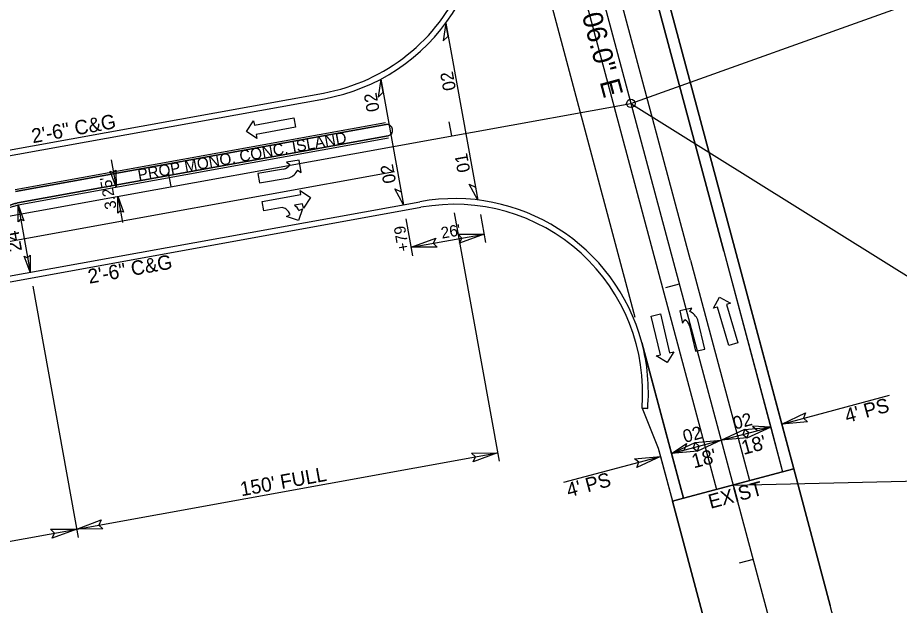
# Model space of a CAD drawing. Extents: x 1616561 to 1622460, y 896726 to 899651.
# Drawn here: x 1621262.4 to 1621571.6, y 898035.6 to 898241.6 of the extents above; entities that cross this region are included whole.
import ezdxf

# ---------------------------------------------------------------- set-up
doc = ezdxf.new("R2010")
doc.units = 0
for name, color, linetype in [('Exist Boundary Study Area', 7, 'Continuous'), ('Old_Level_3', 7, 'Continuous'), ('Old_Level_40', 7, 'Continuous'), ('Prop Dimension', 7, 'Continuous'), ('Prop Horizontal Alignment', 7, 'Continuous'), ('Prop Horizontal Alignment Tick Small', 7, 'Continuous'), ('Prop Lane Arrow CELL', 7, 'Continuous'), ('Prop North Arrow NAD83 for Plan Sheets CELL', 7, 'Continuous'), ('Prop Shade Light', 7, 'Continuous'), ('Prop Shade Medium', 7, 'Continuous'), ('Prop Superelevation  Arrow CELL', 7, 'Continuous'), ('Prop Terminator CELL', 7, 'Continuous'), ('Scratch_Level_1', 7, 'Continuous'), ('Sheet Cutting Line CELL', 7, 'Continuous'), ('Sheet North Arrow CELL', 7, 'Continuous'), ('Sheet Sticker Preliminary CELL', 7, 'Continuous')]:
    doc.layers.add(name, color=color, linetype=linetype)

msp = doc.modelspace()

# ---------------------------------------------------------------- linework, layer by layer
at = {"layer": 'Exist Boundary Study Area'}
for p, q in [((1621261.67, 898180.63), (1621391.56, 898204.14)), ((1621392.28, 898200.21), (1621262.39, 898176.7))]:
    msp.add_line(p, q, dxfattribs=at)
msp.add_arc((1621391.92, 898202.18), 2, 280.2599, 100.2599, dxfattribs=at)
msp.add_spline([(1621262.39, 898176.7), (1621261.08, 898176.3), (1621260.43, 898176.1), (1621259.78, 898175.9), (1621259.13, 898175.7), (1621258.48, 898175.5), (1621257.83, 898175.3), (1621257.18, 898175.1), (1621256.53, 898174.9), (1621255.88, 898174.7), (1621255.23, 898174.5), (1621254.58, 898174.3), (1621253.93, 898174.1), (1621253.28, 898173.9), (1621252.63, 898173.7), (1621251.98, 898173.5), (1621251.33, 898173.29), (1621250.68, 898173.09), (1621250.03, 898172.89), (1621249.38, 898172.69), (1621248.73, 898172.49), (1621248.08, 898172.29), (1621247.43, 898172.09), (1621246.78, 898171.89), (1621246.13, 898171.69), (1621245.47, 898171.49), (1621244.82, 898171.29), (1621244.17, 898171.09), (1621243.52, 898170.89), (1621242.87, 898170.69), (1621242.22, 898170.49), (1621241.57, 898170.29), (1621240.92, 898170.09), (1621240.27, 898169.89), (1621239.62, 898169.69), (1621238.97, 898169.49), (1621238.32, 898169.29), (1621237.67, 898169.09), (1621237.02, 898168.89), (1621236.37, 898168.69), (1621235.72, 898168.49), (1621235.07, 898168.29), (1621234.42, 898168.09), (1621233.77, 898167.89), (1621233.12, 898167.69), (1621232.47, 898167.49), (1621231.82, 898167.29), (1621231.17, 898167.09), (1621230.51, 898166.89), (1621229.86, 898166.69), (1621229.21, 898166.49), (1621228.56, 898166.29), (1621227.91, 898166.09), (1621227.26, 898165.89), (1621226.61, 898165.69), (1621225.96, 898165.49), (1621225.31, 898165.29), (1621224.66, 898165.09), (1621224.01, 898164.89), (1621223.36, 898164.69), (1621222.71, 898164.49), (1621222.06, 898164.29), (1621221.41, 898164.09), (1621220.76, 898163.89), (1621220.11, 898163.69), (1621219.46, 898163.49), (1621218.81, 898163.29), (1621218.16, 898163.09), (1621217.51, 898162.89), (1621216.86, 898162.69), (1621216.21, 898162.49), (1621215.55, 898162.29), (1621214.9, 898162.09), (1621214.25, 898161.89)], degree=3, dxfattribs=at)
at = {"layer": 'Old_Level_3'}
for p, q in [((1621498.38, 898156.58), (1621460.96, 898296.37)), ((1621449.37, 898293.27), (1621486.78, 898153.48)), ((1621437.78, 898290.17), (1621478.87, 898136.64)), ((1621261.54, 898181.37), (1621391.43, 898204.88)), ((1621262.52, 898175.96), (1621392.41, 898199.47)), ((1621166.26, 898146.34), (1621394.55, 898187.66)), ((1621498.38, 898156.58), (1621519.06, 898079.31)), ((1621486.78, 898153.48), (1621507.47, 898076.2))]:
    msp.add_line(p, q, dxfattribs=at)
msp.add_spline([(1621214.39, 898161.15), (1621215.04, 898161.35), (1621215.69, 898161.55), (1621216.34, 898161.75), (1621216.99, 898161.95), (1621217.64, 898162.15), (1621218.29, 898162.35), (1621218.94, 898162.55), (1621219.59, 898162.75), (1621220.24, 898162.95), (1621220.89, 898163.15), (1621221.54, 898163.35), (1621222.19, 898163.55), (1621222.84, 898163.75), (1621223.49, 898163.95), (1621224.14, 898164.15), (1621224.79, 898164.35), (1621225.44, 898164.55), (1621226.1, 898164.75), (1621226.75, 898164.95), (1621227.4, 898165.15), (1621228.05, 898165.35), (1621228.7, 898165.55), (1621229.35, 898165.75), (1621230, 898165.95), (1621230.65, 898166.15), (1621231.3, 898166.35), (1621231.95, 898166.55), (1621232.6, 898166.75), (1621233.25, 898166.95), (1621233.9, 898167.15), (1621234.55, 898167.35), (1621235.2, 898167.55), (1621235.85, 898167.75), (1621236.5, 898167.95), (1621237.15, 898168.15), (1621237.8, 898168.35), (1621238.45, 898168.55), (1621239.1, 898168.75), (1621239.75, 898168.95), (1621240.4, 898169.15), (1621241.06, 898169.35), (1621241.71, 898169.55), (1621242.36, 898169.76), (1621243.01, 898169.96), (1621243.66, 898170.16), (1621244.31, 898170.36), (1621244.96, 898170.56), (1621245.61, 898170.76), (1621246.26, 898170.96), (1621246.91, 898171.16), (1621247.56, 898171.36), (1621248.21, 898171.56), (1621248.86, 898171.76), (1621249.51, 898171.96), (1621250.16, 898172.16), (1621250.81, 898172.36), (1621251.46, 898172.56), (1621252.11, 898172.76), (1621252.76, 898172.96), (1621253.41, 898173.16), (1621254.06, 898173.36), (1621254.71, 898173.56), (1621255.36, 898173.76), (1621256.02, 898173.96), (1621256.67, 898174.16), (1621257.32, 898174.36), (1621257.97, 898174.56), (1621258.62, 898174.76), (1621259.27, 898174.96), (1621259.92, 898175.16), (1621260.57, 898175.36), (1621261.22, 898175.56), (1621262.52, 898175.96)], degree=3, dxfattribs=at)
at = {"layer": 'Old_Level_40'}
for p, q in [((1621530.65, 898082.41), (1621534.52, 898083.44)), ((1621534.52, 898083.44), (1621547.33, 898035.56)), ((1621495.88, 898073.1), (1621530.65, 898082.41)), ((1621492.01, 898072.07), (1621495.88, 898073.1)), ((1621502.92, 898031.33), (1621492.01, 898072.07))]:
    msp.add_line(p, q, dxfattribs=at)
at = {"layer": 'Prop Dimension'}
for p, q in [((1621295.18, 898191.72), (1621296.91, 898182.18)), ((1621297.49, 898178.99), (1621299.14, 898169.83)), ((1621262.52, 898175.96), (1621266.79, 898152.34)), ((1621415.45, 898173.21), (1621431.23, 898086.08)), ((1621267.68, 898147.42), (1621283.62, 898059.37)), ((1621530.32, 898099.12), (1621568.12, 898109.21)), ((1621509.07, 898093.44), (1621526.46, 898098.08)), ((1621491.68, 898088.79), (1621509.07, 898093.44)), ((1621283.09, 898062.32), (1621430.69, 898089.04)), ((1621453.92, 898078.71), (1621487.81, 898087.76)), ((1621184.69, 898044.51), (1621283.09, 898062.32))]:
    msp.add_line(p, q, dxfattribs=at)
at = {"layer": 'Prop Horizontal Alignment'}
for p, q in [((1621476.41, 898300.51), (1621513.83, 898160.72)), ((1621513.83, 898160.72), (1621534.52, 898083.44)), ((1621481.33, 898104.68), (1621487.05, 898090.62)), ((1621481.33, 898104.68), (1621483.33, 898104.52)), ((1621487.05, 898090.62), (1621492.01, 898072.07)), ((1621530.65, 898082.41), (1621534.52, 898083.44)), ((1621534.52, 898083.44), (1621547.33, 898035.56)), ((1621492.01, 898072.07), (1621495.88, 898073.1)), ((1621492.01, 898072.07), (1621502.92, 898031.33))]:
    msp.add_line(p, q, dxfattribs=at)
msp.add_arc((1621415.56, 898110.17), 68, 355.2351, 14.985, dxfattribs=at)
at = {"layer": 'Prop Horizontal Alignment Tick Small'}
for p, q in [((1621019.59, 898151.82), (1621369.62, 898215.16)), ((1621042.54, 898109.72), (1621403.81, 898175.11)), ((1621483.33, 898104.52), (1621481.33, 898104.68))]:
    msp.add_line(p, q, dxfattribs=at)
for centre, radius, start, end in [((1621357.86, 898280.11), 66, 280.2581, 33.5864), ((1621415.56, 898110.17), 66, 355.2351, 100.2599), ((1621415.56, 898110.17), 68, 355.2351, 14.985)]:
    msp.add_arc(centre, radius, start, end, dxfattribs=at)
at = {"layer": 'Prop Lane Arrow CELL'}
for p, q in [((1621345.42, 898203.95), (1621359.2, 898206.44)), ((1621359.2, 898206.44), (1621359.79, 898203.19)), ((1621342.62, 898201.71), (1621345.15, 898205.42)), ((1621345.15, 898205.42), (1621345.42, 898203.95)), ((1621346.28, 898199.22), (1621342.62, 898201.71)), ((1621359.79, 898203.19), (1621346.01, 898200.7)), ((1621346.01, 898200.7), (1621346.28, 898199.22)), ((1621361.08, 898191.67), (1621356.64, 898190.94)), ((1621356.64, 898190.94), (1621357.86, 898190.09)), ((1621361.8, 898187.33), (1621361.08, 898191.67)), ((1621355.6, 898188.52), (1621346.58, 898186.94)), ((1621360.58, 898188.18), (1621361.8, 898187.33)), ((1621346.58, 898186.94), (1621347.16, 898183.69)), ((1621347.16, 898183.69), (1621357.55, 898185.51)), ((1621348.16, 898177.13), (1621361.73, 898179.59)), ((1621361.73, 898179.59), (1621361.47, 898181.06)), ((1621361.47, 898181.06), (1621365.08, 898178.52)), ((1621365.08, 898178.52), (1621362.59, 898174.87)), ((1621348.74, 898173.88), (1621348.16, 898177.13)), ((1621362.32, 898176.34), (1621359.52, 898175.83)), ((1621362.59, 898174.87), (1621362.32, 898176.34)), ((1621355.09, 898175.03), (1621348.74, 898173.88)), ((1621356.67, 898171.91), (1621357.98, 898172.56)), ((1621362.33, 898174.62), (1621360.85, 898170.44)), ((1621360.97, 898173.96), (1621362.33, 898174.62)), ((1621360.85, 898170.44), (1621356.67, 898171.91)), ((1621506.37, 898139.71), (1621508.45, 898143.61)), ((1621508.45, 898143.61), (1621512.41, 898141.5)), ((1621512.41, 898141.5), (1621510.97, 898141.07)), ((1621498.84, 898139.79), (1621494.55, 898138.83)), ((1621494.55, 898138.83), (1621495.53, 898134.44)), ((1621498.06, 898138.53), (1621498.84, 898139.79)), ((1621507.8, 898140.13), (1621506.37, 898139.71)), ((1621511.77, 898126.71), (1621507.8, 898140.13)), ((1621510.97, 898141.07), (1621514.94, 898127.64)), ((1621484.57, 898136.97), (1621487.78, 898137.73)), ((1621487.79, 898123.35), (1621484.57, 898136.97)), ((1621487.78, 898137.73), (1621491, 898124.11)), ((1621495.53, 898134.44), (1621496.32, 898135.7)), ((1621503.33, 898125.39), (1621500.9, 898135.65)), ((1621498.01, 898133.53), (1621500.12, 898124.63)), ((1621514.94, 898127.64), (1621511.77, 898126.71)), ((1621486.33, 898123), (1621487.79, 898123.35)), ((1621490.17, 898120.68), (1621486.33, 898123)), ((1621492.46, 898124.45), (1621490.17, 898120.68)), ((1621491, 898124.11), (1621492.46, 898124.45)), ((1621500.12, 898124.63), (1621503.33, 898125.39))]:
    msp.add_line(p, q, dxfattribs=at)
for centre, radius, start, end in [((1621355.04, 898191.73), 3.28, 279.9792, 329.6374), ((1621355.87, 898190.47), 5.25, 288.6553, 333.967), ((1621356.85, 898172.31), 4.43, 21.8508, 52.7294), ((1621354.9, 898172.51), 2.52, 49.3331, 85.6451), ((1621353.86, 898170.9), 4.43, 21.9696, 52.8232), ((1621496.04, 898133.69), 5.25, 21.9812, 67.2929), ((1621494.84, 898132.79), 3.28, 13.3051, 62.9633)]:
    msp.add_arc(centre, radius, start, end, dxfattribs=at)
at = {"layer": 'Prop North Arrow NAD83 for Plan Sheets CELL'}
for points in [[(1621412.56, 898239.71), (1621411.66, 898233.45), (1621413.39, 898235.16)], [(1621389.7, 898220.02), (1621388.81, 898213.76), (1621390.53, 898215.47)], [(1621423.79, 898177.67), (1621420.76, 898183.21), (1621422.97, 898182.22)], [(1621397.67, 898176.03), (1621394.63, 898181.58), (1621396.84, 898180.58)], [(1621526.33, 898098.04), (1621520.02, 898098.43), (1621521.87, 898096.85)], [(1621491.68, 898088.79), (1621496.96, 898092.27), (1621496.14, 898089.99)]]:
    msp.add_lwpolyline(points, close=True, dxfattribs=at)
at = {"layer": 'Prop Shade Light'}
for p, q in [((1621472.55, 898299.48), (1621509.97, 898159.69)), ((1621513.83, 898160.72), (1621476.41, 898300.51)), ((1621483.33, 898104.52), (1621481.33, 898104.68)), ((1621481.33, 898104.68), (1621487.05, 898090.62)), ((1621530.65, 898082.41), (1621534.52, 898083.44)), ((1621534.52, 898083.44), (1621530.65, 898082.41)), ((1621547.33, 898035.56), (1621534.52, 898083.44)), ((1621530.65, 898082.41), (1621495.88, 898073.1)), ((1621495.88, 898073.1), (1621492.01, 898072.07)), ((1621492.01, 898072.07), (1621495.88, 898073.1)), ((1621492.01, 898072.07), (1621502.92, 898031.33)), ((1621554.57, 898008.51), (1621547.33, 898035.56))]:
    msp.add_line(p, q, dxfattribs=at)
for points in [[(1621534.52, 898083.44), (1621530.32, 898099.12), (1621513.83, 898160.72)], [(1621509.97, 898159.69), (1621526.46, 898098.08), (1621530.65, 898082.41)], [(1621495.88, 898073.1), (1621491.68, 898088.79), (1621481.25, 898127.75)], [(1621487.05, 898090.62), (1621487.81, 898087.76), (1621492.01, 898072.07)]]:
    msp.add_lwpolyline(points, dxfattribs=at)
msp.add_arc((1621415.56, 898110.17), 68, 355.2351, 14.985, dxfattribs=at)
at = {"layer": 'Prop Shade Medium'}
for p, q in [((1621391.56, 898204.14), (1621261.67, 898180.63)), ((1621262.39, 898176.7), (1621392.28, 898200.21))]:
    msp.add_line(p, q, dxfattribs=at)
msp.add_arc((1621391.92, 898202.18), 2, 280.2599, 100.2599, dxfattribs=at)
msp.add_spline([(1621246.34, 898171.76), (1621246.78, 898171.89), (1621247.43, 898172.09), (1621248.08, 898172.29), (1621248.73, 898172.49), (1621249.38, 898172.69), (1621250.03, 898172.89), (1621250.68, 898173.09), (1621251.33, 898173.29), (1621251.98, 898173.5), (1621252.63, 898173.7), (1621253.28, 898173.9), (1621253.93, 898174.1), (1621254.58, 898174.3), (1621255.23, 898174.5), (1621255.88, 898174.7), (1621256.53, 898174.9), (1621257.18, 898175.1), (1621257.83, 898175.3), (1621258.48, 898175.5), (1621259.13, 898175.7), (1621259.78, 898175.9), (1621260.43, 898176.1), (1621261.08, 898176.3), (1621262.39, 898176.7)], degree=3, dxfattribs=at)
at = {"layer": 'Prop Superelevation  Arrow CELL'}
for p, q in [((1621414.64, 898200.19), (1621413.75, 898205.11)), ((1621316.23, 898182.38), (1621315.34, 898187.3)), ((1621494.4, 898148.22), (1621489.57, 898146.93)), ((1621520.26, 898051.62), (1621515.43, 898050.33))]:
    msp.add_line(p, q, dxfattribs=at)
at = {"layer": 'Prop Terminator CELL'}
for p, q in [((1621509.97, 898159.69), (1621472.55, 898299.48)), ((1621019.95, 898149.85), (1621369.97, 898213.19)), ((1621042.18, 898111.69), (1621403.45, 898177.08)), ((1621509.97, 898159.69), (1621530.65, 898082.41)), ((1621481.25, 898127.75), (1621495.88, 898073.1)), ((1621495.88, 898073.1), (1621530.65, 898082.41))]:
    msp.add_line(p, q, dxfattribs=at)
for points in [[(1621296.86, 898188.12), (1621296.91, 898182.18), (1621294.84, 898187.79), (1621295.99, 898187.24)], [(1621297.54, 898173.05), (1621297.49, 898178.99), (1621299.56, 898173.38), (1621298.4, 898173.93)], [(1621262.57, 898170.02), (1621262.52, 898175.96), (1621264.59, 898170.36), (1621263.43, 898170.91)], [(1621409.5, 898161.19), (1621400.37, 898161.11), (1621408.99, 898164.3), (1621408.14, 898162.52)], [(1621416.82, 898165.67), (1621425.95, 898165.74), (1621417.33, 898162.56), (1621418.18, 898164.34)], [(1621266.74, 898158.28), (1621266.79, 898152.34), (1621264.72, 898157.95), (1621265.88, 898157.4)], [(1621539.42, 898099.94), (1621530.32, 898099.12), (1621538.65, 898103), (1621537.95, 898101.15)], [(1621518.16, 898094.26), (1621509.07, 898093.44), (1621517.4, 898097.32), (1621516.7, 898095.48)], [(1621517.36, 898097.26), (1621526.46, 898098.08), (1621518.13, 898094.2), (1621518.82, 898096.04)], [(1621500.77, 898089.62), (1621491.68, 898088.79), (1621500.01, 898092.67), (1621499.31, 898090.83)], [(1621499.97, 898092.61), (1621509.07, 898093.44), (1621500.74, 898089.56), (1621501.43, 898091.4)], [(1621421.56, 898088.96), (1621430.69, 898089.04), (1621422.07, 898085.85), (1621422.92, 898087.63)], [(1621478.72, 898086.94), (1621487.81, 898087.76), (1621479.48, 898083.88), (1621480.18, 898085.72)], [(1621292.22, 898062.4), (1621283.09, 898062.32), (1621291.71, 898065.51), (1621290.86, 898063.73)], [(1621273.96, 898062.24), (1621283.09, 898062.32), (1621274.47, 898059.13), (1621275.32, 898060.91)]]:
    msp.add_lwpolyline(points, close=True, dxfattribs=at)
for centre, start, end in [((1621357.86, 898280.11), 280.2581, 13.8393), ((1621415.56, 898110.17), 14.985, 100.2599)]:
    msp.add_arc(centre, 68, start, end, dxfattribs=at)
at = {"layer": 'Sheet Cutting Line CELL'}
for p, q in [((1621287.55, 898921.02), (1621727.49, 897277.4)), ((1620889.86, 898105.2), (1621477.45, 898211.56))]:
    msp.add_line(p, q, dxfattribs=at)
at = {"layer": 'Sheet North Arrow CELL'}
for p, q in [((1621477.45, 898211.56), (1621735.86, 898304.31)), ((1621477.45, 898211.56), (1621583.22, 898145.43)), ((1621513.26, 898077.75), (1621747.4, 898082.97))]:
    msp.add_line(p, q, dxfattribs=at)
msp.add_circle((1621477.45, 898211.56), 1.5, dxfattribs=at)
at = {"layer": 'Sheet Sticker Preliminary CELL'}
for p, q in [((1621412.56, 898239.71), (1621423.79, 898177.67)), ((1621389.7, 898220.02), (1621397.67, 898176.03)), ((1621424.7, 898172.65), (1621426.49, 898162.79)), ((1621398.56, 898171.11), (1621400.9, 898158.16)), ((1621400.37, 898161.11), (1621425.95, 898165.74))]:
    msp.add_line(p, q, dxfattribs=at)

# ---------------------------------------------------------------- texts
at = {"layer": 'Prop Dimension'}
for s, height, rotation, p in [('2\'-6" C&G', 5.044, 10.3779, (1621267.75, 898197.56)), ('PROP MONO. CONC. ISLAND', 4, 10.2599, (1621304.87, 898184.48)), ("3.25'", 4, 100.2599, (1621297.11, 898174.8)), ("24'", 5, 100.1765, (1621263.98, 898159.94)), ('2\'-6" C&G', 5.044, 10.3779, (1621287.52, 898148.3)), ("4' PS", 5, 15.039, (1621553.2, 898099.46)), ("18'", 5, 15.039, (1621516.95, 898088.29)), ("18'", 5, 15.039, (1621499.51, 898083.56)), ("150' FULL", 5, 10.2599, (1621340.88, 898073.79)), ("4' PS", 5, 15.039, (1621455.61, 898073.38)), ('EXIST', 5, 14.985, (1621505.36, 898069.38))]:
    msp.add_text(s, height=height, rotation=rotation, dxfattribs=at).set_placement(p)
at = {"layer": 'Prop North Arrow NAD83 for Plan Sheets CELL'}
for p in [(1621513.89, 898097.14), (1621496.33, 898092.48)]:
    msp.add_text('02', height=4.5, rotation=14.9555, dxfattribs=at).set_placement(p)
at = {"layer": 'Scratch_Level_1'}
msp.add_text('S 14%%d 59\' 06.0" E', height=7, rotation=284.985, dxfattribs=at).set_placement((1621449.74, 898281.5))
at = {"layer": 'Sheet Sticker Preliminary CELL'}
for s, height, rotation, p in [('02', 4.5, 100.2581, (1621416.13, 898216.43)), ('02', 4.5, 100.2581, (1621389.35, 898209)), ('01', 4.5, 100.2581, (1621421.14, 898187.76)), ('02', 4.5, 100.2581, (1621395.12, 898183.92)), ('+79', 4, 99.8945, (1621399.73, 898159.97)), ("26'", 4, 10.2599, (1621411.19, 898164.1))]:
    msp.add_text(s, height=height, rotation=rotation, dxfattribs=at).set_placement(p)

doc.saveas('drawing.dxf')
